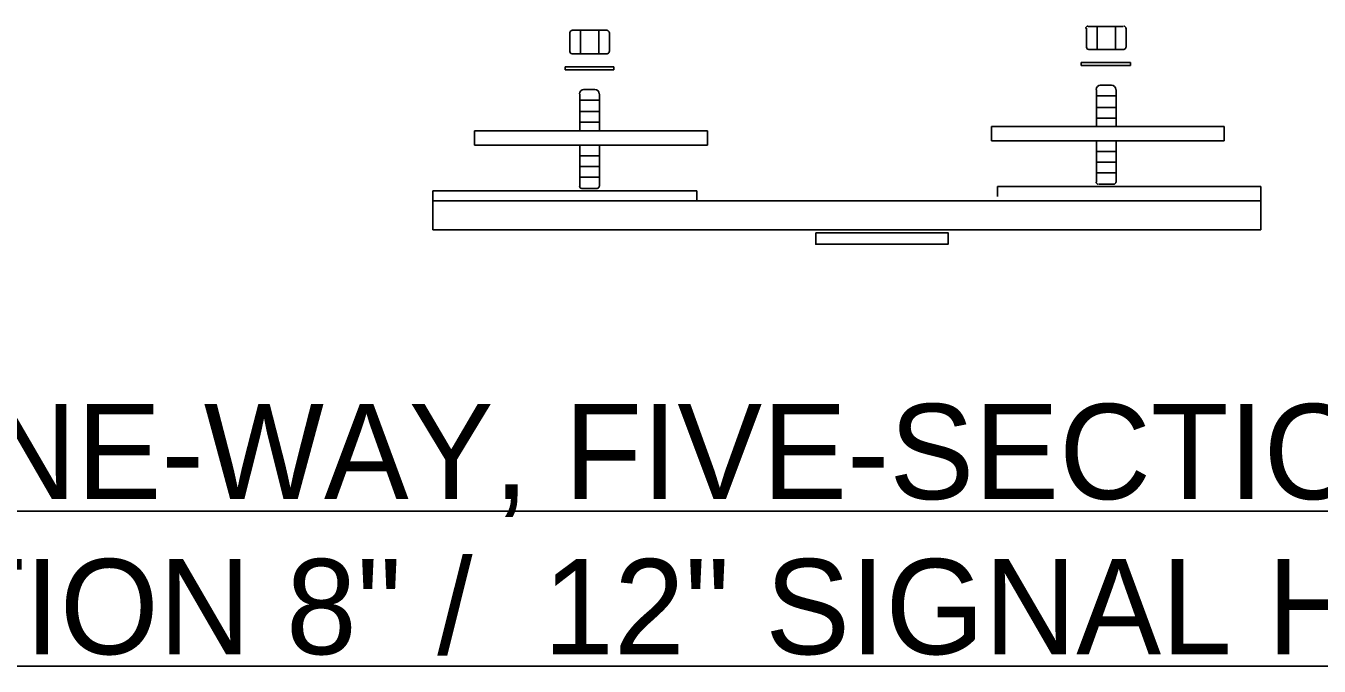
# Model space of a CAD drawing. Extents: x -1316.3 to -1303.1, y 2853.3 to 2863.3.
# Drawn here: x -1305.424 to -1304.065, y 2857.233 to 2857.905 of the extents above; entities that cross this region are included whole.
import ezdxf

# ---------------------------------------------------------------- set-up
doc = ezdxf.new("R2010")
doc.units = 0
for name, color, linetype in [('DETL-DIMS', 7, 'Continuous'), ('DETL-LINE', 7, 'Continuous'), ('DETL-TITL', 7, 'Continuous')]:
    doc.layers.add(name, color=color, linetype=linetype)

msp = doc.modelspace()

# ---------------------------------------------------------------- linework, layer by layer
at = {"layer": 'DETL-DIMS'}
msp.add_lwpolyline([(-1304.5941, 2857.6881), (-1304.4549, 2857.6881), (-1304.4549, 2857.6761), (-1304.5941, 2857.6761)], close=True, dxfattribs=at)
at = {"layer": 'DETL-LINE'}
for p, q in [((-1304.8526, 2857.8985), (-1304.8526, 2857.8785)), ((-1304.8502, 2857.9009), (-1304.8134, 2857.9009)), ((-1304.8414, 2857.9009), (-1304.8414, 2857.8761)), ((-1304.8222, 2857.9009), (-1304.8222, 2857.8761)), ((-1304.811, 2857.8785), (-1304.811, 2857.8985)), ((-1304.3094, 2857.903), (-1304.3094, 2857.883)), ((-1304.3078, 2857.9046), (-1304.271, 2857.9046)), ((-1304.2982, 2857.9054), (-1304.2982, 2857.8806)), ((-1304.279, 2857.9054), (-1304.279, 2857.8806)), ((-1304.2678, 2857.883), (-1304.2678, 2857.903)), ((-1304.8502, 2857.8761), (-1304.8134, 2857.8761)), ((-1304.307, 2857.8806), (-1304.2702, 2857.8806)), ((-1304.8574, 2857.8625), (-1304.8062, 2857.8625)), ((-1304.8574, 2857.8625), (-1304.8574, 2857.8593)), ((-1304.8574, 2857.8593), (-1304.8062, 2857.8593)), ((-1304.8062, 2857.8625), (-1304.8062, 2857.8593)), ((-1304.315, 2857.867), (-1304.315, 2857.8638)), ((-1304.315, 2857.867), (-1304.263, 2857.867)), ((-1304.315, 2857.8638), (-1304.263, 2857.8638)), ((-1304.263, 2857.867), (-1304.263, 2857.8638)), ((-1304.8422, 2857.7953), (-1304.8422, 2857.8337)), ((-1304.8382, 2857.8385), (-1304.8262, 2857.8385)), ((-1304.8214, 2857.7953), (-1304.8214, 2857.8337)), ((-1304.299, 2857.7998), (-1304.299, 2857.8382)), ((-1304.299, 2857.8318), (-1304.2782, 2857.8318)), ((-1304.295, 2857.843), (-1304.283, 2857.843)), ((-1304.2782, 2857.7998), (-1304.2782, 2857.8382)), ((-1304.8422, 2857.8273), (-1304.8214, 2857.8273)), ((-1304.299, 2857.8198), (-1304.2782, 2857.8198)), ((-1304.8422, 2857.8153), (-1304.8214, 2857.8153)), ((-1304.8422, 2857.8041), (-1304.8214, 2857.8041)), ((-1304.299, 2857.8086), (-1304.2782, 2857.8086)), ((-1304.9526, 2857.7953), (-1304.7078, 2857.7953)), ((-1304.9526, 2857.7801), (-1304.9526, 2857.7953)), ((-1304.7078, 2857.7801), (-1304.7078, 2857.7953)), ((-1304.4094, 2857.7846), (-1304.4094, 2857.7998)), ((-1304.4094, 2857.7998), (-1304.1646, 2857.7998)), ((-1304.1646, 2857.7846), (-1304.1646, 2857.7998)), ((-1304.9526, 2857.7801), (-1304.7078, 2857.7801)), ((-1304.8422, 2857.7369), (-1304.8422, 2857.7801)), ((-1304.8214, 2857.7369), (-1304.8214, 2857.7801)), ((-1304.4094, 2857.7846), (-1304.1646, 2857.7846)), ((-1304.299, 2857.7414), (-1304.299, 2857.7846)), ((-1304.2782, 2857.7414), (-1304.2782, 2857.7846)), ((-1304.8422, 2857.7689), (-1304.8214, 2857.7689)), ((-1304.299, 2857.7734), (-1304.2782, 2857.7734)), ((-1304.299, 2857.7622), (-1304.2782, 2857.7622)), ((-1304.8422, 2857.7577), (-1304.8214, 2857.7577)), ((-1304.299, 2857.751), (-1304.2782, 2857.751)), ((-1304.8422, 2857.7465), (-1304.8214, 2857.7465)), ((-1304.403, 2857.7366), (-1304.1262, 2857.7366)), ((-1304.403, 2857.7262), (-1304.403, 2857.7366)), ((-1304.2966, 2857.739), (-1304.2806, 2857.739)), ((-1304.1262, 2857.7366), (-1304.1262, 2857.6913)), ((-1304.9966, 2857.7321), (-1304.719, 2857.7321)), ((-1304.9966, 2857.6913), (-1304.9966, 2857.7321)), ((-1304.9966, 2857.7217), (-1304.1262, 2857.7217)), ((-1304.8398, 2857.7345), (-1304.8238, 2857.7345)), ((-1304.719, 2857.7217), (-1304.719, 2857.7321)), ((-1304.9966, 2857.6913), (-1304.1262, 2857.6913))]:
    msp.add_line(p, q, dxfattribs=at)
for centre, radius, start, end in [((-1304.8502, 2857.8983), 0.00231, 90, 180), ((-1304.8134, 2857.8983), 0.00231, 0, 90), ((-1304.3079, 2857.9028), 0.00231, 90, 180), ((-1304.2703, 2857.9028), 0.00231, 0, 90), ((-1304.8502, 2857.8784), 0.00231, 180, 270), ((-1304.8134, 2857.8784), 0.00231, 270, 0), ((-1304.3071, 2857.8829), 0.00231, 180, 270), ((-1304.2703, 2857.8829), 0.00231, 270, 0), ((-1304.8377, 2857.8339), 0.00462, 90, 180), ((-1304.8262, 2857.8339), 0.00462, 0, 90), ((-1304.2946, 2857.8384), 0.00462, 90, 180), ((-1304.2831, 2857.8384), 0.00462, 0, 90), ((-1304.84, 2857.7369), 0.00231, 180, 270), ((-1304.8239, 2857.7369), 0.00231, 270, 0), ((-1304.297, 2857.7414), 0.00231, 180, 270), ((-1304.2808, 2857.7414), 0.00231, 270, 0)]:
    msp.add_arc(centre, radius, start, end, dxfattribs=at)
at = {"layer": 'DETL-TITL'}
for p, q in [((-1305.5779, 2857.3958), (-1303.7031, 2857.3958)), ((-1306.1361, 2857.2329), (-1303.1362, 2857.2329))]:
    msp.add_line(p, q, dxfattribs=at)

# ---------------------------------------------------------------- texts
for s, p in [('ONE-WAY, FIVE-SECTION', (-1305.5716, 2857.4083)), ('COMBINATION 8" /  12" SIGNAL HEADS', (-1306.1316, 2857.2454))]:
    msp.add_text(s, height=0.1, dxfattribs=at).set_placement(p)

doc.saveas('drawing.dxf')
